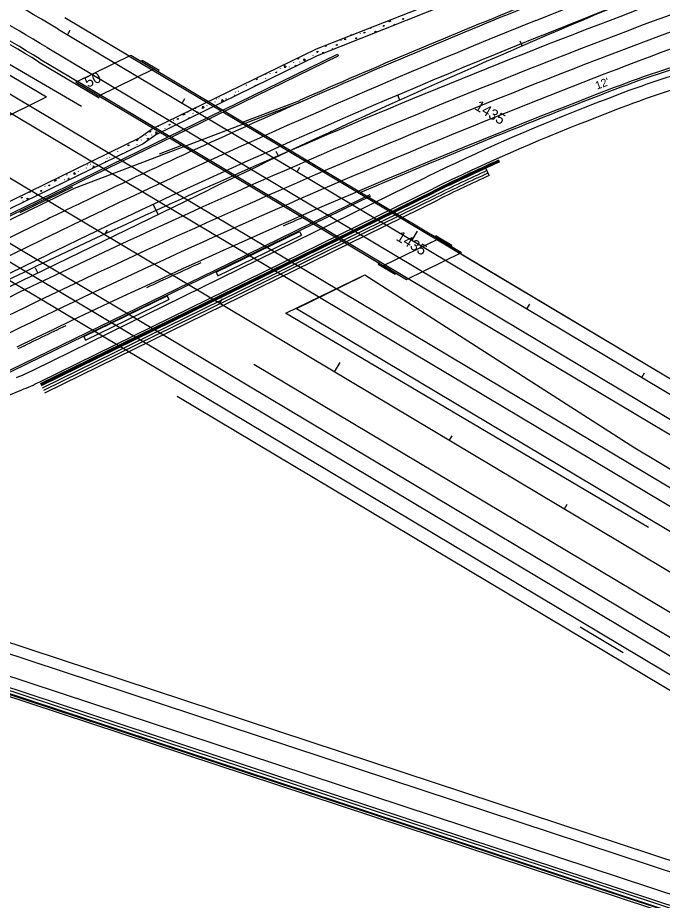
# Model space of a CAD drawing. Extents: x 2339272 to 2351734, y 366540 to 375057.
# Drawn here: x 2349299 to 2349780, y 367549 to 368209 of the extents above; entities that cross this region are included whole.
import ezdxf

# ---------------------------------------------------------------- set-up
doc = ezdxf.new("R2010")
doc.units = 0
for name, color, linetype in [('RD_HC_Cl', 7, 'Continuous'), ('RD_HC_CL_Rel', 7, 'Continuous'), ('RD_HC_Data_Tic', 7, 'Continuous'), ('RD_HC_Data_Tic_Rel', 7, 'Continuous'), ('RD_HC_TX_Rel_Sta50', 7, 'Continuous'), ('RD_HC_TX_Sta50', 7, 'Continuous'), ('RD_PD_Bridge', 7, 'Continuous'), ('RD_PD_Final_LnLine', 7, 'Continuous'), ('RD_PD_Final_TrvlWay', 7, 'Continuous'), ('RD_PD_FOC', 7, 'Continuous'), ('RD_PD_GR', 7, 'Continuous'), ('RD_PD_GrRail', 7, 'Continuous'), ('RD_PD_MedBWall', 7, 'Continuous'), ('RD_PD_NOISE-WALL-GM', 7, 'Continuous'), ('RD_PD_PaveShd', 7, 'Continuous'), ('RD_PD_SW', 7, 'Continuous'), ('RD_PD_WallCut', 7, 'Continuous'), ('RD_PD_WallFill', 7, 'Continuous')]:
    doc.layers.add(name, color=color, linetype=linetype)

msp = doc.modelspace()

# ---------------------------------------------------------------- linework, layer by layer
at = {"layer": 'RD_HC_Cl'}
for p, q in [((2346281.57, 369885.43), (2351112.4, 367003.22)), ((2348794.11, 367765.14), (2349441.47, 368080.05))]:
    msp.add_line(p, q, dxfattribs=at)
msp.add_arc((2351947.82, 362927.74), 5729.58, 109.588035, 115.940729, dxfattribs=at)
at = {"layer": 'RD_HC_CL_Rel'}
msp.add_line((2349328.8, 368200.11), (2349833.31, 367899.11), dxfattribs=at)
for centre, radius, start, end in [((2344717.52, 360471.2), 9000, 59.178507, 60.642806), ((2349988.36, 367521.67), 680, 98.07798, 111.03168)]:
    msp.add_arc(centre, radius, start, end, dxfattribs=at)
at = {"layer": 'RD_HC_Data_Tic'}
for p, q in [((2349675.77, 368187.58), (2349674.19, 368191.25)), ((2349584.32, 368147.12), (2349582.67, 368150.77)), ((2349493.59, 368105.08), (2349491.88, 368108.69)), ((2349403.54, 368061.6), (2349400.04, 368068.79)), ((2349363.76, 368046.51), (2349365.8, 368049.95)), ((2349313.62, 368017.85), (2349311.87, 368021.45)), ((2349449.63, 367995.28), (2349451.68, 367998.71)), ((2349535.51, 367944.04), (2349539.61, 367950.91)), ((2349621.39, 367892.8), (2349623.44, 367896.24)), ((2349707.26, 367841.57), (2349709.31, 367845))]:
    msp.add_line(p, q, dxfattribs=at)
at = {"layer": 'RD_HC_Data_Tic_Rel'}
for p, q in [((2349335.73, 368195.98), (2349337.78, 368199.42)), ((2349421.61, 368144.74), (2349423.66, 368148.18)), ((2349507.49, 368093.51), (2349509.53, 368096.94)), ((2349593.36, 368042.27), (2349597.46, 368049.14)), ((2349679.24, 367991.03), (2349681.29, 367994.47)), ((2349765.12, 367939.8), (2349767.17, 367943.23))]:
    msp.add_line(p, q, dxfattribs=at)
at = {"layer": 'RD_PD_Bridge'}
for p, q in [((2349342.13, 368160.58), (2349383.21, 368180.61)), ((2349382, 368180.02), (2349450.75, 368139)), ((2349383.21, 368180.61), (2349630.39, 368033.13)), ((2349391.15, 368175.95), (2349391.66, 368176.8)), ((2349404.43, 368169.18), (2349391.66, 368176.8)), ((2349359.3, 368150.33), (2349400.39, 368170.36)), ((2349403.29, 368168.63), (2349404.43, 368169.18)), ((2349342.13, 368160.58), (2349410.89, 368119.55)), ((2349343.33, 368161.17), (2349590.52, 368013.69)), ((2349452.04, 368138.23), (2349629.18, 368032.54)), ((2349412.17, 368118.79), (2349589.31, 368013.1)), ((2349446.98, 368018.49), (2349509.32, 368048.89)), ((2349448.3, 368015.8), (2349510.63, 368046.19)), ((2349509.32, 368048.89), (2349510.63, 368046.19)), ((2349572.13, 368023.35), (2349613.22, 368043.38)), ((2349611.45, 368045.67), (2349610.31, 368045.11)), ((2349611.45, 368045.67), (2349623.1, 368038.72)), ((2349613.97, 368043), (2349622.59, 368037.86)), ((2349589.31, 368013.1), (2349630.39, 368033.13)), ((2349622.59, 368037.86), (2349623.1, 368038.72)), ((2349569.23, 368025.09), (2349568.08, 368024.53)), ((2349568.08, 368024.53), (2349580.86, 368016.91)), ((2349572.75, 368022.91), (2349581.37, 368017.76)), ((2349446.98, 368018.49), (2349448.3, 368015.8)), ((2349581.37, 368017.76), (2349580.86, 368016.91)), ((2349348.09, 367970.27), (2349410.38, 368000.65)), ((2349410.38, 368000.65), (2349411.7, 367997.95)), ((2349349.4, 367967.58), (2349411.7, 367997.95)), ((2349348.09, 367970.27), (2349349.4, 367967.58))]:
    msp.add_line(p, q, dxfattribs=at)
at = {"layer": 'RD_PD_Final_LnLine'}
for p, q in [((2348620.92, 368538.62), (2351133.92, 367039.29)), ((2348577.88, 368466.48), (2351090.88, 366967.15)), ((2349685.87, 368206.54), (2349804.82, 368254.4)), ((2349690.35, 368195.41), (2349809.3, 368243.27)), ((2349076.83, 368154.82), (2349846.26, 367695.75)), ((2348932.13, 367868.98), (2349312.02, 368053.77)), ((2348784.92, 367784.02), (2349317.27, 368042.98)), ((2348790.17, 367773.23), (2349322.52, 368032.19))]:
    msp.add_line(p, q, dxfattribs=at)
for centre, radius, start, end in [((2351783.35, 362853.29), 5729.58, 109.588035, 115.940729), ((2351783.35, 362853.29), 5717.58, 109.58804, 115.94073), ((2351783.35, 362853.29), 5705.58, 109.58804, 115.94073), ((2351828.87, 362879.88), 5741.58, 111.915714, 115.940729), ((2351783.35, 362853.29), 5693.58, 110.25944, 115.94073), ((2351828.87, 362879.88), 5729.58, 111.915714, 115.940729), ((2351828.87, 362879.88), 5753.58, 113.768054, 115.561063), ((2351828.87, 362879.88), 5753.58, 115.561063, 115.940729)]:
    msp.add_arc(centre, radius, start, end, dxfattribs=at)
at = {"layer": 'RD_PD_Final_TrvlWay'}
for p, q in [((2348626.93, 368549.01), (2350811.17, 367245.82)), ((2349328.8, 368200.11), (2349833.31, 367899.11)), ((2349320.61, 368186.37), (2349825.11, 367885.37)), ((2349341.05, 368081.24), (2349509.98, 368145.47)), ((2349008.27, 367919.36), (2349341.05, 368081.24)), ((2349178.28, 368080.32), (2349840.11, 367685.45)), ((2349186.88, 367768.08), (2350139.35, 367454)), ((2349185.32, 367751.75), (2350134.34, 367438.81))]:
    msp.add_line(p, q, dxfattribs=at)
for centre, radius, start, end in [((2344717.52, 360471.2), 9000, 59.178507, 60.642806), ((2344717.52, 360471.2), 8984, 59.178507, 60.415096), ((2351828.87, 362879.88), 5753.58, 111.915714, 113.768054), ((2349988.36, 367521.67), 680, 98.07798, 111.03168), ((2351783.35, 362853.29), 5681.58, 111.03168, 115.94073)]:
    msp.add_arc(centre, radius, start, end, dxfattribs=at)
at = {"layer": 'RD_PD_FOC'}
for p, q in [((2349466.73, 368130.63), (2349509.44, 368146.87)), ((2349404.58, 368107), (2349421.43, 368113.41)), ((2349300.37, 368063.12), (2349339.83, 368082.31))]:
    msp.add_line(p, q, dxfattribs=at)
for centre, radius, start, end in [((2351828.87, 362879.88), 5755.08, 111.915714, 113.768054), ((2349988.36, 367521.67), 678.5, 98.07798, 111.03168), ((2351783.35, 362853.29), 5680.08, 111.03168, 113.09877), ((2351783.35, 362853.29), 5680.08, 113.57163, 113.73484), ((2351783.35, 362853.29), 5680.08, 114.4154, 114.86723), ((2351783.35, 362853.29), 5680.08, 115.53838, 115.94073)]:
    msp.add_arc(centre, radius, start, end, dxfattribs=at)
at = {"layer": 'RD_PD_GR'}
for p, q in [((2349333.93, 368208.7), (2349381.89, 368180.08)), ((2349621.98, 368036.84), (2349838.43, 367907.7)), ((2349590.52, 368013.69), (2349819.99, 367876.78))]:
    msp.add_line(p, q, dxfattribs=at)
at = {"layer": 'RD_PD_GrRail'}
for p, q in [((2349142.77, 368261.41), (2349346.2, 368142.48)), ((2349558.12, 368016.57), (2349759.86, 367887.11)), ((2349769.99, 367827.67), (2349498.86, 367987.72)), ((2349759.83, 367887.06), (2350238.85, 367601.26))]:
    msp.add_line(p, q, dxfattribs=at)
at = {"layer": 'RD_PD_MedBWall'}
for p, q in [((2349235.32, 368033.93), (2349537.7, 368181.41)), ((2349235.87, 368032.8), (2349538.23, 368180.27)), ((2349537.7, 368181.41), (2349538.23, 368180.27)), ((2349518.54, 368055.33), (2349562.12, 368076.58)), ((2349519.82, 368054.56), (2349562.67, 368075.45)), ((2349446.22, 368020.07), (2349518.54, 368055.33)), ((2349446.77, 368018.94), (2349519.82, 368054.56)), ((2349257.43, 367928.02), (2349446.22, 368020.07)), ((2349257.98, 367926.9), (2349446.77, 368018.94)), ((2349182.18, 367742.25), (2350081.34, 367445.75)), ((2349181.45, 367740.04), (2350080.6, 367443.54))]:
    msp.add_line(p, q, dxfattribs=at)
at = {"layer": 'RD_PD_NOISE-WALL-GM'}
for p, q in [((2349179.87, 367740.03), (2350080.45, 367443.06)), ((2349180.83, 367738.14), (2350079.98, 367441.64))]:
    msp.add_line(p, q, dxfattribs=at)
at = {"layer": 'RD_PD_PaveShd'}
for p, q in [((2348633, 368559.35), (2349320.08, 368149.43)), ((2349333.93, 368208.7), (2349381.89, 368180.08)), ((2349315.48, 368177.79), (2349360.7, 368150.81)), ((2349277.31, 368128.37), (2349320.08, 368149.43)), ((2349612.02, 368042.78), (2349838.43, 367907.7)), ((2349573.34, 368023.94), (2349815.39, 367879.53)), ((2349498.97, 367987.72), (2349558.12, 368016.57)), ((2349506.94, 367991.36), (2349555.29, 368014.89)), ((2349506.94, 367991.36), (2350200.36, 367577.64)), ((2349475.16, 367949.69), (2350173.67, 367533.02)), ((2349417.91, 367925.7), (2349835.16, 367676.76)), ((2349242.31, 367758.23), (2350063.21, 367487.53)), ((2349718.94, 367753.35), (2349751.25, 367734.17)), ((2349182.81, 367744.15), (2350053.19, 367457.14))]:
    msp.add_line(p, q, dxfattribs=at)
msp.add_arc((2344717.52, 360471.2), 8974, 59.178507, 60.415096, dxfattribs=at)
at = {"layer": 'RD_PD_SW'}
for p, q in [((2349522.02, 368185.49), (2349616.72, 368222.79)), ((2349522.76, 368180.29), (2349621.94, 368219.82)), ((2349576.22, 368205.53), (2349576.43, 368206.92)), ((2349579.51, 368207.47), (2349579.53, 368207.74)), ((2349583.37, 368206.94), (2349583.53, 368206.82)), ((2349561.79, 368200.48), (2349561.9, 368201.2)), ((2349565.08, 368202.42), (2349565.08, 368202.45)), ((2349568.94, 368201.89), (2349569.1, 368201.77)), ((2349540.07, 368191.79), (2349540.23, 368191.67)), ((2349547.35, 368195.42), (2349547.36, 368195.47)), ((2349548.21, 368195.81), (2349547.38, 368195.43)), ((2349554.5, 368196.84), (2349554.66, 368196.72)), ((2349400.04, 368126.02), (2349522.02, 368185.49)), ((2349525.63, 368186.74), (2349525.79, 368186.62)), ((2349533.92, 368185.25), (2349533.94, 368185.53)), ((2349548.37, 368190.49), (2349548.37, 368190.58)), ((2349402.6, 368121.71), (2349522.76, 368180.29)), ((2349519.48, 368180.2), (2349519.5, 368180.47)), ((2349523.85, 368180.72), (2349523.86, 368180.79)), ((2349501.43, 368171.94), (2349501.53, 368171.71)), ((2349505.05, 368175.15), (2349505.07, 368175.42)), ((2349509.4, 368175.47), (2349509.43, 368175.74)), ((2349515.86, 368176.99), (2349515.89, 368176.94)), ((2349483.82, 368166.21), (2349483.7, 368166.81)), ((2349486.99, 368166.89), (2349487.1, 368166.66)), ((2349490.61, 368170.1), (2349490.62, 368170.18)), ((2349494.97, 368170.42), (2349494.99, 368170.69)), ((2349498.43, 368168.43), (2349498.44, 368168.49)), ((2349469.55, 368158.11), (2349469.57, 368158.38)), ((2349475.84, 368158.19), (2349476, 368158.07)), ((2349477.85, 368158.83), (2349478.01, 368158.71)), ((2349483.98, 368163.16), (2349484, 368163.44)), ((2349461.4, 368153.14), (2349461.56, 368153.02)), ((2349463.42, 368153.78), (2349463.58, 368153.66)), ((2349446.1, 368145.61), (2349446.13, 368145.88)), ((2349446.97, 368148.09), (2349447.13, 368147.97)), ((2349448.98, 368148.73), (2349449.14, 368148.61)), ((2349454.54, 368147.89), (2349454.56, 368148.16)), ((2349460.54, 368150.66), (2349460.56, 368150.93)), ((2349431.67, 368140.56), (2349431.69, 368140.83)), ((2349440.11, 368142.83), (2349440.13, 368143.11)), ((2349443.97, 368142.3), (2349444.13, 368142.18)), ((2349415.1, 368132.2), (2349415.26, 368132.08)), ((2349422.38, 368135.84), (2349422.56, 368137)), ((2349425.67, 368137.78), (2349425.69, 368138.05)), ((2349429.53, 368137.25), (2349429.69, 368137.13)), ((2349400.04, 368126.02), (2349389.83, 368118.81)), ((2349403.65, 368127.43), (2349403.69, 368127.8)), ((2349408.95, 368125.67), (2349408.97, 368125.94)), ((2349389.83, 368118.81), (2349003.02, 367930.15)), ((2349402.6, 368121.71), (2349392.39, 368114.49)), ((2349394.51, 368120.62), (2349394.53, 368120.89)), ((2349398.87, 368120.93), (2349398.89, 368121.21)), ((2349392.39, 368114.49), (2349005.21, 367925.65)), ((2349376.48, 368112.3), (2349376.57, 368112.13)), ((2349384.43, 368115.88), (2349384.46, 368116.16)), ((2349387.72, 368116.73), (2349387.52, 368117.68)), ((2349387.88, 368113.68), (2349387.9, 368113.95)), ((2349390.89, 368117.4), (2349391, 368117.18)), ((2349373.45, 368108.63), (2349373.47, 368108.9)), ((2349379.74, 368108.71), (2349379.9, 368108.59)), ((2349381.75, 368109.35), (2349381.79, 368109.32)), ((2349350.87, 368098.61), (2349351.03, 368098.49)), ((2349352.88, 368099.25), (2349353.04, 368099.12)), ((2349358.44, 368098.4), (2349358.46, 368098.67)), ((2349359.01, 368103.58), (2349359.03, 368103.78)), ((2349364.44, 368101.18), (2349364.46, 368101.45)), ((2349365.3, 368103.66), (2349365.46, 368103.54)), ((2349367.32, 368104.3), (2349367.48, 368104.18)), ((2349344.01, 368093.35), (2349344.03, 368093.62)), ((2349347.87, 368092.82), (2349347.9, 368092.79)), ((2349350, 368096.13), (2349350.03, 368096.4)), ((2349310.65, 367945.44), (2349604.47, 368089.68)), ((2349326.28, 368086.35), (2349326.52, 368087.93)), ((2349329.57, 368088.3), (2349329.59, 368088.57)), ((2349333.43, 368087.77), (2349333.59, 368087.65)), ((2349335.57, 368091.07), (2349335.59, 368091.35)), ((2349315.06, 367936.47), (2349608.87, 368080.7)), ((2349319, 368082.72), (2349319.16, 368082.6)), ((2349312.85, 368076.18), (2349312.87, 368076.46)), ((2349302.77, 368071.45), (2349302.79, 368071.72)), ((2348973.08, 367796.86), (2349301.62, 367930.44))]:
    msp.add_line(p, q, dxfattribs=at)
for points in [[(2349576.58, 368206.98), (2349577.44, 368206.07), (2349576.25, 368205.54)], [(2349586.36, 368207.22), (2349586.44, 368207.99), (2349587.11, 368207.78), (2349586.36, 368207.22)], [(2349557.49, 368197.12), (2349557.58, 368197.88), (2349558.24, 368197.68), (2349557.49, 368197.12)], [(2349562.58, 368201.47), (2349563.01, 368201.02), (2349561.81, 368200.49)], [(2349565.77, 368197.92), (2349565.86, 368198.68), (2349566.52, 368198.47), (2349565.77, 368197.92)], [(2349571.92, 368202.17), (2349572.01, 368202.94), (2349572.67, 368202.73), (2349571.92, 368202.17)], [(2349580.23, 368203.2), (2349580.29, 368203.73), (2349580.96, 368203.52), (2349580.84, 368203.44)], [(2349543.06, 368192.07), (2349543.14, 368192.83), (2349543.8, 368192.62), (2349543.06, 368192.07)], [(2349551.34, 368192.87), (2349551.43, 368193.63), (2349552.09, 368193.42), (2349551.34, 368192.87)], [(2349528.62, 368187.02), (2349528.71, 368187.78), (2349529.37, 368187.57), (2349528.62, 368187.02)], [(2349536.91, 368187.81), (2349536.99, 368188.58), (2349537.65, 368188.37), (2349536.91, 368187.81)], [(2349541.3, 368187.68), (2349541.24, 368187.99), (2349541.61, 368187.8)], [(2349508.04, 368177.71), (2349508.12, 368178.48), (2349508.78, 368178.27), (2349508.04, 368177.71)], [(2349512.68, 368176.31), (2349512.37, 368177.88), (2349513.65, 368177.24), (2349512.71, 368176.33)], [(2349522.47, 368182.76), (2349522.56, 368183.53), (2349523.22, 368183.32), (2349522.47, 368182.76)], [(2349527, 368181.98), (2349526.8, 368182.94), (2349527.95, 368182.36)], [(2349498.25, 368171.26), (2349497.93, 368172.83), (2349499.21, 368172.19), (2349498.27, 368171.28)], [(2349506.06, 368172.42), (2349506.15, 368173.18), (2349506.81, 368172.97), (2349506.06, 368172.42)], [(2349484.58, 368167.24), (2349484.78, 368167.14), (2349483.84, 368166.23)], [(2349491.63, 368167.37), (2349491.71, 368168.13), (2349492.37, 368167.92), (2349491.63, 368167.37)], [(2349477.19, 368162.32), (2349477.28, 368163.08), (2349477.94, 368162.87), (2349477.19, 368162.32)], [(2349451.25, 368145.94), (2349451.49, 368147.52), (2349452.47, 368146.49), (2349451.28, 368145.95)], [(2349432.52, 368137.53), (2349432.61, 368138.3), (2349433.27, 368138.09), (2349432.52, 368137.53)], [(2349436.82, 368140.89), (2349437.06, 368142.47), (2349438.04, 368141.43), (2349436.84, 368140.9)], [(2349418.09, 368132.48), (2349418.17, 368133.25), (2349418.83, 368133.04), (2349418.09, 368132.48)], [(2349422.87, 368137.16), (2349423.6, 368136.38), (2349422.41, 368135.85)], [(2349426.37, 368133.3), (2349426.46, 368134.04), (2349427.12, 368133.83), (2349426.44, 368133.33)], [(2349404.2, 368128.05), (2349404.4, 368127.99), (2349403.65, 368127.43)], [(2349411.94, 368128.23), (2349412.02, 368128.99), (2349412.68, 368128.78), (2349411.94, 368128.23)], [(2349416.27, 368128.38), (2349416.27, 368128.4), (2349416.3, 368128.39)], [(2349395.53, 368117.88), (2349395.61, 368118.65), (2349396.27, 368118.44), (2349395.53, 368117.88)], [(2349397.5, 368123.18), (2349397.59, 368123.94), (2349398.25, 368123.73), (2349397.5, 368123.18)], [(2349402.15, 368121.78), (2349401.83, 368123.35), (2349403.11, 368122.71), (2349402.17, 368121.8)], [(2349381.09, 368112.83), (2349381.18, 368113.6), (2349381.84, 368113.39), (2349381.09, 368112.83)], [(2349388.08, 368117.95), (2349388.68, 368117.66), (2349387.74, 368116.74)], [(2349340.72, 368091.41), (2349340.96, 368092.99), (2349341.94, 368091.95), (2349340.74, 368091.41)], [(2349355.15, 368096.46), (2349355.39, 368098.04), (2349356.37, 368097), (2349355.18, 368096.47)], [(2349326.53, 368087.93), (2349327.5, 368086.9), (2349326.31, 368086.36)], [(2349336.42, 368088.05), (2349336.51, 368088.81), (2349337.17, 368088.6), (2349336.42, 368088.05)], [(2349315.84, 368078.74), (2349315.92, 368079.51), (2349316.58, 368079.3), (2349315.84, 368078.74)], [(2349321.99, 368083), (2349322.07, 368083.76), (2349322.73, 368083.55), (2349321.99, 368083)], [(2349330.32, 368084.22), (2349330.36, 368084.56), (2349330.76, 368084.43)], [(2349301.4, 368073.69), (2349301.49, 368074.46), (2349302.15, 368074.25), (2349301.4, 368073.69)], [(2349306.04, 368072.37), (2349305.73, 368073.86), (2349307.01, 368073.22), (2349306.24, 368072.47)], [(2349307.55, 368077.95), (2349307.64, 368078.71), (2349308.3, 368078.5), (2349307.55, 368077.95)]]:
    msp.add_lwpolyline(points, dxfattribs=at)
for centre, radius, start, end in [((2349988.36, 367521.67), 674, 98.07798, 111.03168), ((2349988.36, 367521.67), 664, 98.07798, 111.03168), ((2351783.35, 362853.29), 5675.58, 111.03168, 111.30456), ((2350269.88, 366734.2), 1510, 111.30456, 116.14693), ((2351783.35, 362853.29), 5665.58, 111.03168, 111.30456), ((2350269.88, 366734.2), 1500, 111.30456, 116.14693), ((2349222.52, 368124.98), 200, 292.12665, 296.14693), ((2349222.52, 368124.98), 210, 292.12665, 296.14693)]:
    msp.add_arc(centre, radius, start, end, dxfattribs=at)
at = {"layer": 'RD_PD_WallCut'}
for p, q in [((2349315.48, 368177.79), (2349360.7, 368150.81)), ((2349314.29, 368175.78), (2349359.5, 368148.8))]:
    msp.add_line(p, q, dxfattribs=at)
for radius in [8971.67, 8974]:
    msp.add_arc((2344717.52, 360471.2), radius, 59.178507, 60.415096, dxfattribs=at)
at = {"layer": 'RD_PD_WallFill'}
for p, q in [((2349657.97, 368102.07), (2349658.58, 368100.7)), ((2349651.05, 368090.72), (2349648.56, 368096.17)), ((2349315.72, 367935.12), (2349609.53, 368079.36)), ((2349315.94, 367934.67), (2349609.75, 368078.91)), ((2349316.16, 367934.22), (2349609.97, 368078.46)), ((2349316.38, 367933.77), (2349610.19, 368078.01)), ((2349317.26, 367931.98), (2349611.08, 368076.21)), ((2349318.15, 367930.18), (2349611.96, 368074.42)), ((2349319.03, 367928.39), (2349612.84, 368072.62))]:
    msp.add_line(p, q, dxfattribs=at)
for radius, start in [(1498.5, 114.10151), (1498, 114.10151), (1497.5, 114.10151), (1497, 114.10151), (1495, 114.52218), (1493, 114.52218), (1491, 114.52218)]:
    msp.add_arc((2350269.88, 366734.2), radius, start, 116.14693, dxfattribs=at)

# ---------------------------------------------------------------- texts
at = {"layer": 'RD_HC_TX_Rel_Sta50'}
msp.add_text('1435', height=8, rotation=329.17851, dxfattribs=at).set_placement((2349639.53, 368140.49))
at = {"layer": 'RD_HC_TX_Sta50'}
for s, rotation, p in [('50', 25.94073, (2349351.09, 368156.18)), ('1435', 329.17851, (2349580.85, 368042.75))]:
    msp.add_text(s, height=8, rotation=rotation, dxfattribs=at).set_placement(p)
at = {"layer": 'RD_PD_Final_TrvlWay'}
msp.add_text("12'", height=6, rotation=20.60283, dxfattribs=at).set_placement((2349731.6, 368154.82))

doc.saveas('drawing.dxf')
